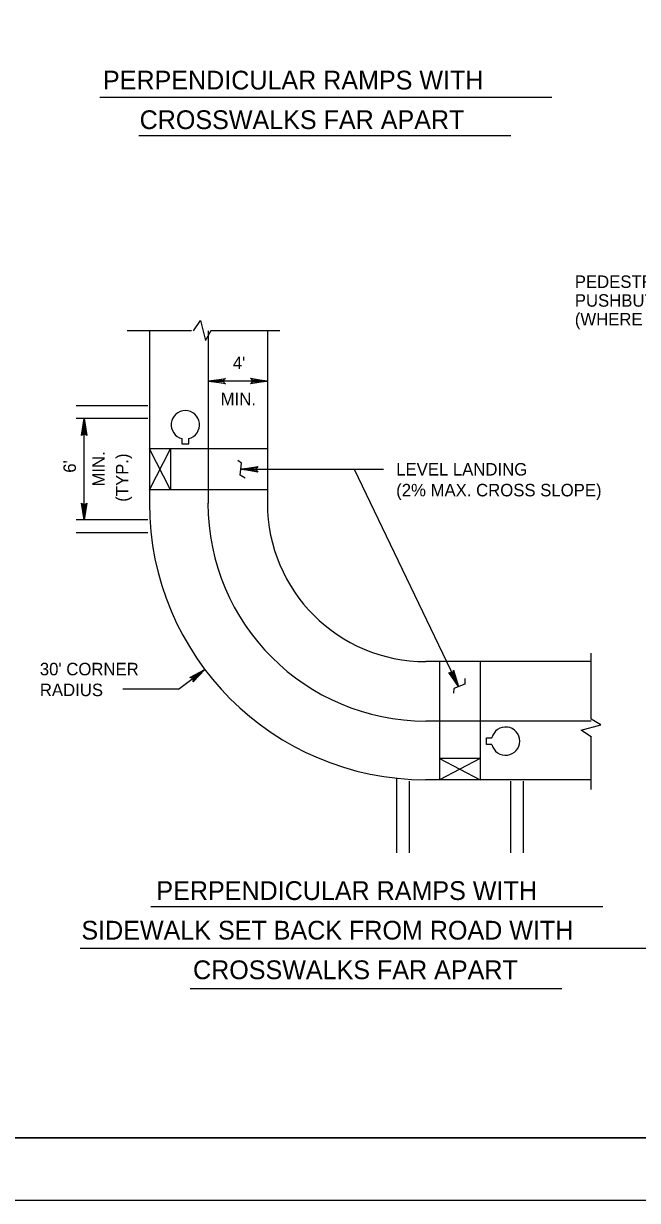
# Model space of a CAD drawing. Extents: x -344 to 940, y 22 to 1233.
# Drawn here: x 263.8 to 411, y 22.2 to 304.6 of the extents above; entities that cross this region are included whole.
import ezdxf

# ---------------------------------------------------------------- set-up
doc = ezdxf.new("R2010")
doc.units = 0
for name, color, linetype in [('1', 7, 'Continuous'), ('2', 7, 'Continuous'), ('Default', 7, 'Continuous'), ('PLT-BNDY', 7, 'Continuous')]:
    doc.layers.add(name, color=color, linetype=linetype)

msp = doc.modelspace()

# ---------------------------------------------------------------- linework, layer by layer
at = {"layer": '1'}
for p, q in [((861.86, 37.17), (75.86, 37.17)), ((75.86, 37.17), (661.86, 37.17))]:
    msp.add_line(p, q, dxfattribs=at)
at = {"layer": '2'}
for p, q in [((282.03, 286.88), (390.47, 286.88)), ((291.44, 277.68), (380.65, 277.68)), ((304.07, 230.84), (288.6, 230.84)), ((293.95, 230.84), (293.95, 189.46)), ((308.11, 189.46), (308.11, 230.84)), ((325.23, 230.84), (308.7, 230.84)), ((322.27, 230.84), (322.27, 189.46)), ((322.27, 218.8), (308.11, 218.8)), ((293.58, 212.84), (276.41, 212.84)), ((293.58, 209.77), (276.41, 209.77)), ((278.29, 185.46), (278.29, 209.77)), ((301.75, 205), (301.75, 203.7)), ((301.75, 203.7), (303.41, 203.7)), ((303.41, 203.7), (303.41, 205)), ((322.27, 202.51), (293.95, 202.51)), ((299.02, 192.72), (293.95, 202.51)), ((293.95, 192.72), (299.02, 202.51)), ((299.02, 202.51), (299.02, 192.72)), ((315.95, 197.61), (350.11, 197.61)), ((343.11, 197.61), (368.11, 145.51)), ((322.27, 192.72), (293.95, 192.72)), ((293.58, 185.46), (276.41, 185.46)), ((293.58, 182.39), (276.41, 182.39)), ((399.94, 137.68), (399.94, 153.49)), ((399.94, 151.47), (360.27, 151.47)), ((363.53, 151.47), (363.53, 123.14)), ((373.32, 151.47), (373.32, 123.14)), ((300.96, 144.83), (307.28, 149.58)), ((300.96, 144.83), (287.57, 144.83)), ((399.94, 137.2), (360.27, 137.2)), ((374.82, 131.55), (374.82, 133.21)), ((374.82, 133.21), (376.12, 133.21)), ((399.94, 120.76), (399.94, 133.43)), ((376.12, 131.55), (374.82, 131.55)), ((373.32, 128.21), (363.53, 128.21)), ((363.53, 128.21), (373.32, 123.14)), ((373.32, 128.21), (363.53, 123.14)), ((353.2, 123.51), (353.2, 105.6)), ((356.27, 122.77), (356.27, 105.6)), ((399.94, 123.14), (360.27, 123.14)), ((380.58, 122.77), (380.58, 105.6)), ((383.65, 122.77), (383.65, 105.6)), ((294.3, 92.71), (402.74, 92.71)), ((277.32, 82.69), (420.95, 82.69)), ((303.72, 73.07), (392.92, 73.07))]:
    msp.add_line(p, q, dxfattribs=at)
for points in [[(304.5, 230.81), (306.18, 233.29), (307.45, 228.55), (308.8, 230.92)], [(311.97, 218.31), (311.83, 218.59), (308.11, 218.8), (311.97, 218.31), (312.17, 218.14), (308.11, 218.8), (311.82, 218.98), (311.96, 219.26), (308.11, 218.8), (312.17, 219.44), (311.96, 219.26)], [(318.42, 219.28), (318.56, 219), (322.27, 218.8), (318.42, 219.28), (318.22, 219.45), (322.27, 218.8), (318.56, 218.61), (318.43, 218.34), (322.27, 218.8), (318.22, 218.15), (318.43, 218.34)], [(277.81, 205.91), (278.09, 206.05), (278.29, 209.77), (277.81, 205.91), (277.64, 205.71), (278.29, 209.77), (278.47, 206.05), (278.75, 205.92), (278.29, 209.77), (278.94, 205.71), (278.75, 205.92)], [(316.94, 195.51), (315.72, 196.2), (316.08, 199.05), (315.14, 199.69)], [(319.81, 197.13), (319.66, 197.41), (315.95, 197.61), (319.81, 197.13), (320, 196.96), (315.95, 197.61), (319.66, 197.8), (319.79, 198.07), (315.95, 197.61), (320, 198.26), (319.79, 198.07)], [(278.78, 189.32), (278.5, 189.17), (278.29, 185.46), (278.78, 189.32), (278.94, 189.52), (278.29, 185.46), (278.11, 189.17), (277.83, 189.31), (278.29, 185.46), (277.65, 189.52), (277.83, 189.31)], [(303.9, 147.65), (304.18, 147.51), (307.28, 149.58), (303.9, 147.65), (303.64, 147.66), (307.28, 149.58), (304.42, 147.2), (304.48, 146.9), (307.28, 149.58), (304.42, 146.62), (304.48, 146.9)], [(366.87, 149.2), (366.68, 148.95), (368.11, 145.51), (366.87, 149.2), (366.94, 149.45), (368.11, 145.51), (366.33, 148.78), (366.03, 148.78), (368.11, 145.51), (365.77, 148.89), (366.03, 148.78)], [(369.61, 147.44), (369.66, 146.09), (367.01, 144.99), (366.92, 143.86)], [(400.02, 133.31), (397.54, 135), (402.28, 136.26), (399.91, 137.62)]]:
    msp.add_lwpolyline(points, dxfattribs=at)
for centre, radius, start, end in [((302.58, 208.29), 3.4, 284.1014, 255.8986), ((360.27, 189.46), 66.33, 180, 270), ((360.27, 189.46), 52.26, 180, 270), ((360.27, 189.46), 38, 180, 270), ((379.41, 132.38), 3.4, 194.1014, 165.8986)]:
    msp.add_arc(centre, radius, start, end, dxfattribs=at)
at = {"layer": 'PLT-BNDY'}
msp.add_lwpolyline([(35.86, 616.17), (876.86, 616.17), (876.86, 22.17), (35.86, 22.17)], close=True, dxfattribs=at)

# ---------------------------------------------------------------- texts
at = {"layer": '2'}
for s, height, p in [('PERPENDICULAR RAMPS WITH', 4.5, (282.82, 288.75)), ('CROSSWALKS FAR APART', 4.5, (291.61, 279.25)), ("4'", 3, (313.97, 221.65)), ('MIN.', 3, (311.05, 213)), ('LEVEL LANDING', 3, (353.16, 196.12)), ('(2% MAX. CROSS SLOPE)', 3, (353.16, 191.12)), ("30' CORNER", 3, (267.67, 148.18)), ('RADIUS', 3, (267.67, 143.18)), ('PERPENDICULAR RAMPS WITH', 4.5, (295.64, 94.27)), ('SIDEWALK SET BACK FROM ROAD WITH', 4.5, (277.64, 84.77)), ('CROSSWALKS FAR APART', 4.5, (304.42, 75.27))]:
    msp.add_text(s, height=height, dxfattribs=at).set_placement(p)
for s, p in [('MIN.', (283.26, 193.48)), ('(TYP.)', (288.9, 189.82)), ("6'", (276.33, 196.79))]:
    msp.add_text(s, height=3, rotation=90, dxfattribs=at).set_placement(p)
at = {"layer": 'Default'}
for s, p in [('PEDESTRIAN', (396.01, 241.13)), ('PUSHBUTTON', (396.01, 236.63)), ('(WHERE APPLICABLE)', (396.01, 232.13))]:
    msp.add_text(s, height=3, dxfattribs=at).set_placement(p)

doc.saveas('drawing.dxf')
